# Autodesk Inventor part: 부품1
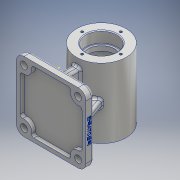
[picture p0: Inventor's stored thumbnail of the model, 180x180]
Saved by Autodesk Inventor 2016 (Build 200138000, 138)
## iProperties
Created: 2019-06
Part Number: 부품1
Material: 알루미늄 6061
Document SubType Name: Modeling
Designer: 605-12
Density: 2.7 g/cm^3
Appearance: 알루미늄 - 평지
Mass: 609.113 g
Surface Area: 624.232 cm^2
Volume: 225.597 cm^3
Author: 605-12
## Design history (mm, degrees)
sketch "스케치1"
  geometry: C1 r 32 at (0, 0); 1 further point
  constraints: 1 centre point, 1 coincident
  dimensions: "d0" = 64 diameter of C1
extrude "돌출1" new body sketch "스케치1" distance "d1" = 90; taper "d2" = 0 deg
sketch "스케치2"
  geometry: C1 r 32 at (0, 0) reference; C2 r 20 at (0, 0); 1 further point
  constraints: 1 centre point, 1 coincident
  dimensions: "d3" = 40 diameter of C2
extrude "돌출2" cut sketch "스케치2" distance "d4" = 15; taper "d5" = 0 deg
sketch "스케치3"
  geometry: C1 r 20 at (0, 0) reference; C2 r 32 at (0, 0) reference; C3 r 17 at (0, 0); 1 further point
  constraints: 1 centre point, 1 coincident
  dimensions: "d6" = 34 diameter of C3
extrude "돌출3" cut sketch "스케치3" distance "d7" = 6; taper "d8" = 0 deg
sketch "스케치4"
  geometry: C1 r 17 at (0, 0) reference; C2 r 32 at (0, 0) reference; C3 r 25 at (0, 0); 1 further point
  constraints: 1 centre point, 1 coincident
  dimensions: "d9" = 50 diameter of C3
extrude "돌출4" cut sketch "스케치4" distance "d10" = 48; taper "d11" = 0 deg
sketch "스케치5"
  geometry: L1 (0, 0)-(0, 37.484); C1 r 25 at (0, 0); 3 further points
  constraints: 2 end point, 1 centre point, 1 coincident, 1 point on line, 1 vertical, 1 vertical alignment, 1 other
  dimensions: "d12" = 50 diameter of C1
hole "구멍1" sketch "스케치5" at (0, 25) diameter "d13" = 3.242; stored, may be unused: countersink angle "d17" = 90 deg, drill point angle "d19" = 118 deg; dims "d14" = 7, "d15" = 4, "d16" = 2, "d18" = 9
node "작업 평면1"
node "작업 평면2"
sketch "스케치6"
  geometry: L1 (-32, -90)-(32, -90) reference; L2 (32, 0)-(32, -90) reference; L3 (-32, 0)-(-32, -90) reference; L4 (45, 0)-(-45, 0); L5 (-45, 0)-(-45, -90); L6 (-45, -90)-(45, -90) reference; L7 (45, -90)-(45, 0) reference; L8 (45, 0)-(-45, -90); L9 (-45, 0)-(45, -90); 2 further points
  constraints: 12 end point, 2 horizontal, 2 midpoint, 2 parallel, 1 perpendicular, 1 vertical
  dimensions: "d24" = 90 distance of L6.end L5.end; "d25" = 90 distance of L5.end L4.end
extrude "돌출5" join sketch "스케치6" distance "d26" = 10; taper "d27" = 0 deg
sketch "스케치7"
  geometry: L1 (32, 0)-(32, -90) reference; L2 (32, -90)-(26.621, -90) reference; L3 (26.621, -90)-(26.621, -81) reference; L4 (26.621, -81)-(25, -80.026) reference; L5 (25, -80.026)-(23.379, -81) reference; L6 (23.379, -81)-(23.379, -90) reference; L7 (23.379, -90)-(20, -90) reference; L8 (20, -90)-(20, -75) reference; L9 (20, -75)-(17, -75) reference; L10 (17, -75)-(17, -69) reference; L11 (17, -69)-(25, -69) reference; L12 (25, -69)-(25, -21) reference; L13 (25, -21)-(17, -21) reference; L14 (17, -21)-(17, -15) reference; L15 (17, -15)-(20, -15) reference; L16 (20, -15)-(20, 0) reference; L17 (20, 0)-(23.379, 0) reference; L18 (23.379, 0)-(23.379, -9) reference; L19 (23.379, -9)-(25, -9.974) reference; L20 (25, -9.974)-(26.621, -9) reference; L21 (26.621, -9)-(26.621, 0) reference; L22 (26.621, 0)-(32, 0) reference; L23 (-32, -90)-(-32, 0) reference; L24 (-32, 0)-(-26.621, 0) reference; L25 (-26.621, 0)-(-26.621, -9) reference; L26 (-26.621, -9)-(-25, -9.974) reference; L27 (-25, -9.974)-(-23.379, -9) reference; L28 (-23.379, -9)-(-23.379, 0) reference; L29 (-23.379, 0)-(-20, 0) reference; L30 (-20, 0)-(-20, -15) reference; L31 (-20, -15)-(-17, -15) reference; L32 (-17, -15)-(-17, -21) reference; L33 (-17, -21)-(-25, -21) reference; L34 (-25, -21)-(-25, -69) reference; L35 (-25, -69)-(-17, -69) reference; L36 (-17, -69)-(-17, -75) reference; L37 (-17, -75)-(-20, -75) reference; L38 (-20, -75)-(-20, -90) reference; L39 (-20, -90)-(-23.379, -90) reference; L40 (-23.379, -90)-(-23.379, -81) reference; L41 (-23.379, -81)-(-25, -80.026) reference; L42 (-25, -80.026)-(-26.621, -81) reference; L43 (-26.621, -81)-(-26.621, -90) reference; L44 (-26.621, -90)-(-32, -90) reference; L45 (-65, 0)-(-55, 0) reference; L46 (-55, 0)-(-55, -90) reference; L47 (-55, -90)-(-65, -90) reference; L48 (-65, -90)-(-65, 0) reference; L49 (32, 0)-(32, -90) reference; L50 (-65, -90)-(-65, 0) reference; L51 (-29.31, -10)-(-29.31, -80) reference; L52 (-29.31, -10)-(-55, -10) reference; L53 (-29.31, -80)-(-55, -80) reference; L54 (-55, -90)-(-55, 0) reference; L55 (-55, -10)-(-55, -80); 1 further point
  constraints: 8 end point, 2 horizontal, 2 point on line, 1 perpendicular, 1 vertical
extrude "돌출6" join sketch "스케치7" stored distance "d30" = 10; taper "d31" = 0 deg
node "작업 평면3"
sketch "스케치8"
  geometry: L1 (45, -55)-(45, -65) reference; L2 (45, -65)-(-45, -65) reference; L3 (-45, -65)-(-45, -55) reference; L4 (-45, -55)-(-5, -55) reference; L5 (-5, -55)-(-5, -31.607) reference; L6 (5, -31.607)-(5, -55) reference; L7 (5, -55)-(45, -55) reference; L8 (-35, -54.99)-(-23.06, -22.186); C1 r 25 at (0, 0) reference; A1 r 32 centre (0, 0) between (5, -31.607) and (-5, -31.607) reference; 1 further point
  constraints: 2 end point, 1 point on circle
feature "리브1" sketch "스케치8" dims "d35" = 1, "d36" = 10, "d37" = 0, "d38" = 0, "d39" = 1, "d40" = 1
node "작업 평면4"
node "작업 평면5"
sketch "스케치9"
  geometry: L1 (-32, -90)-(32, -90) reference; L2 (0, -90)-(0, 0); L3 (-32, 0)-(-32, -90) reference; L4 (-32, -45)-(32, -45); L5 (32, 0)-(32, -90) reference; C1 r 5 at (0, -45)
  constraints: 4 end point, 4 midpoint, 1 centre point, 1 vertical
  dimensions: "d42" = 10 diameter of C1
extrude "돌출7" join sketch "스케치9" stored distance "d43" = 10; taper "d44" = 0 deg
sketch "스케치10"
  geometry: C1 r 5 at (0, 0) reference; 2 further points
  constraints: 1 coincident
hole "구멍2" sketch "스케치10" at (0, 0) diameter "d45" = 4.917; stored, may be unused: countersink angle "d49" = 90 deg, drill point angle "d51" = 118 deg; dims "d46" = 17, "d47" = 4, "d48" = 2, "d50" = 22.1
sketch "스케치12"
  geometry: L1 (-45, -90)-(-45, 0) reference; L2 (-45, 0)-(45, 0) reference; L3 (45, 0)-(45, -90) reference; L4 (45, -90)-(-45, -90) reference; L5 (45, 0)-(45, -90) reference; L6 (-45, -90)-(-45, 0) reference; L7 (-32, -90)-(32, -90) reference; L8 (-40, -85)-(40, -5); L9 (40, -85)-(-40, -5); L10 (26.34, -5)-(-26.34, -5) reference; L11 (40, -71.34)-(40, -18.66) reference; L12 (-40, -18.66)-(-40, -71.34) reference; L13 (-26.34, -85)-(26.34, -85) reference; A1 r 10 centre (35, -10) between (26.34, -5) and (40, -18.66); A2 r 10 centre (35, -80) between (40, -71.34) and (26.34, -85); A3 r 10 centre (-35, -80) between (-26.34, -85) and (-40, -71.34) reference; A4 r 10 centre (-35, -10) between (-40, -18.66) and (-26.34, -5) reference; 6 further points
  constraints: 12 end point, 8 point on circle, 4 centre point, 4 coincident, 3 horizontal, 2 midpoint, 2 parallel, 2 vertical, 1 perpendicular, 2 other
  dimensions: "d65" = 20 diameter of A1; "d66" = 20 diameter of A2
extrude "돌출9" cut sketch "스케치12" distance "d69" = 5; taper "d70" = 0 deg
fillet "모깎기1" dims "d71" = 3
fillet "모깎기2" dims "d72" = 10
fillet "모깎기3" dims "d73" = 2
fillet "모깎기4" dims "d74" = 3
fillet "모깎기5" dims "d75" = 0.6
fillet "모깎기6" dims "d76" = 3
fillet "모깎기7" dims "d77" = 3
fillet "모깎기8" dims "d78" = 3
sketch "스케치13"
  geometry: L1 (0, 0)-(-10, 0) reference; L2 (-10, 7)-(-10, 0) reference; 2 further points
  constraints: 1 other
  dimensions: "d79" = 4 distance from line of L1 point (35, 4); "d80" = 45 distance from line of point (35, 4) L2
feature "엠보싱1" sketch "스케치13" dims "d0" = 64, "d9" = 50, "d81" = 0.5, "d82" = 0
chamfer "모따기1" distance "d83" = 1; stored, may be unused: second distance "d84" = 2, angle "d85" = 45 deg
sketch "스케치14"
  geometry: 1 further point
sketch "스케치15"
  geometry: L1 (-50.126, 10)-(-30, 10); L2 (-35, -2.351)-(-35, 27.367); L3 (-35, 0)-(35, 0) reference; L4 (-45, 80)-(-45, 10) reference; C1 r 4.5 at (-35, 10); 1 further point
  constraints: 4 end point, 2 point on line, 1 centre point, 1 horizontal, 1 vertical
  dimensions: "d86" = 10 distance between parallel lines of L3 L1; "d87" = 10 distance between parallel lines of L4 L2; "d88" = 9 diameter of C1
extrude "돌출10" cut sketch "스케치15" distance "d89" = 10; taper "d90" = 0 deg
node "솔리드1"
pattern_circular "원형 패턴1" dims angle "d21" = 360 deg
mirror "대칭1"
mirror "대칭2"
pattern_linear "직사각형 패턴2" dims "d93" = 70
node "절단 모서리 투영1"
node "절단 모서리 투영2"
node "절단 모서리 투영3"
node "절단 모서리 투영4"
node "절단 모서리 투영5"
node "절단 모서리 투영6"
node "절단 모서리 투영8"
other parameters: "d23" = -65, "d28" = 35, "d29" = 35, "d32" = -45, "d34" = 110 deg
